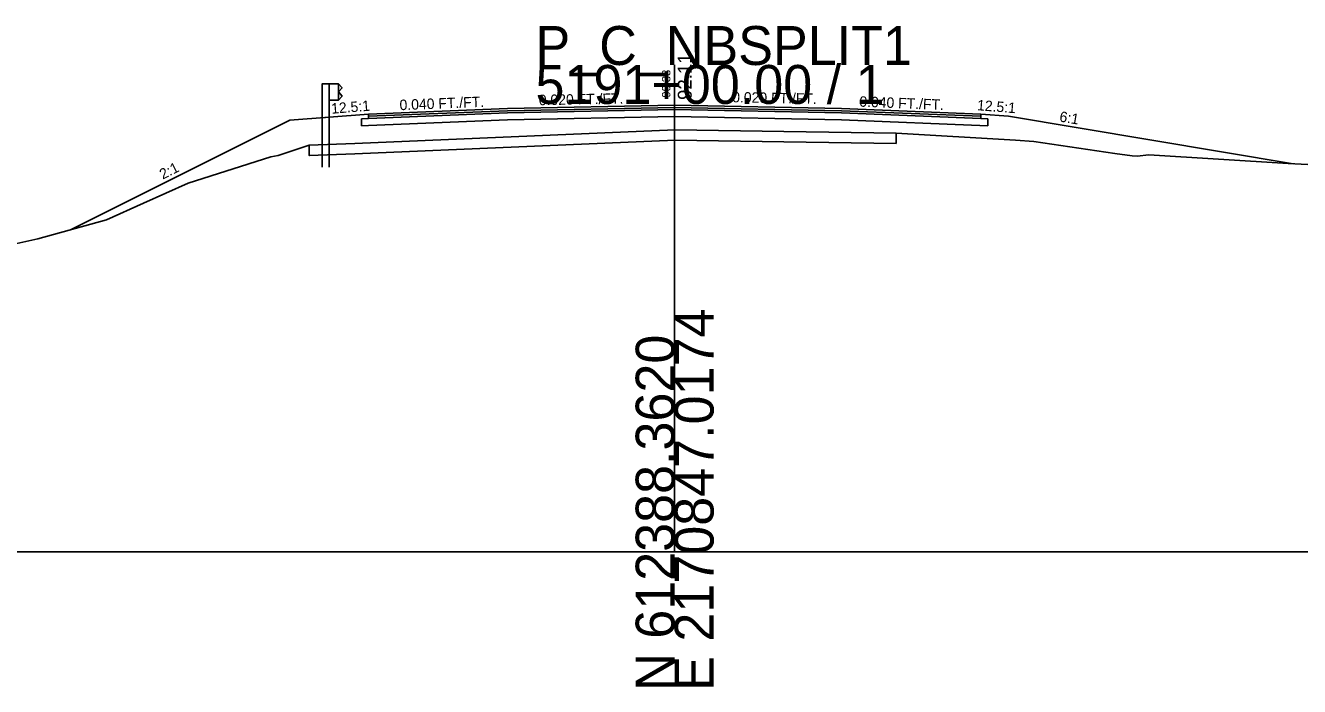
# Model space of a CAD drawing. Extents: x -26 to 1303, y -3010 to 12038.
# Drawn here: x 103.4 to 194.9, y 8990.3 to 9037.8 of the extents above; entities that cross this region are included whole.
import ezdxf

# ---------------------------------------------------------------- set-up
doc = ezdxf.new("R2010")
doc.units = 0
for name, color, linetype in [('RD_GPK_XS_Cell', 7, 'Continuous'), ('RD_PD_Final_TrvlWay', 7, 'Continuous'), ('RD_XS_Base', 7, 'Continuous'), ('RD_XS_ExGround', 7, 'Continuous'), ('RD_XS_ExPaveRet', 7, 'Continuous'), ('RD_XS_GR', 7, 'Continuous'), ('RD_XS_Greenside', 7, 'Continuous'), ('RD_XS_Pave', 7, 'Continuous'), ('RD_XS_PaveOvlay_CP', 7, 'Continuous'), ('RD_XS_TieSlope', 7, 'Continuous'), ('RD_XS_TX_Elev_EX', 7, 'Continuous'), ('RD_XS_TX_Elev_PR', 7, 'Continuous'), ('RD_XS_TX_ShdSlope', 7, 'Continuous'), ('RD_XS_TX_Slope', 7, 'Continuous')]:
    doc.layers.add(name, color=color, linetype=linetype)

msp = doc.modelspace()

# ---------------------------------------------------------------- linework, layer by layer
at = {"layer": 'RD_GPK_XS_Cell'}
for p, q in [((150, 9000), (150, 9035)), ((0, 9000), (150, 9000)), ((150, 9000), (300, 9000))]:
    msp.add_line(p, q, dxfattribs=at)
at = {"layer": 'RD_PD_Final_TrvlWay'}
for p, q in [((125.167, 9031.246), (124.667, 9031.206)), ((124.667, 9031.206), (124.667, 9027.641)), ((125.167, 9027.641), (125.167, 9031.246))]:
    msp.add_line(p, q, dxfattribs=at)
at = {"layer": 'RD_XS_Base'}
for p, q in [((150, 9031.794), (138, 9031.554)), ((150, 9031.794), (150, 9031.953)), ((150, 9031.953), (150, 9031.953)), ((150, 9031.953), (150, 9031.953)), ((150, 9031.953), (150, 9031.294)), ((150, 9031.294), (150, 9031.794)), ((150, 9031.794), (150, 9031.794)), ((150, 9031.794), (150, 9031.794)), ((150, 9031.794), (150, 9031.794)), ((162, 9031.554), (150, 9031.794)), ((128, 9031.154), (127.5, 9031.134)), ((127.5, 9031.134), (127.5, 9031.134)), ((127.5, 9031.134), (127.5, 9030.634)), ((138, 9031.554), (128, 9031.154)), ((128, 9031.154), (128, 9031.154)), ((128, 9030.654), (138, 9031.054)), ((138, 9031.554), (138, 9031.554)), ((138, 9031.054), (150, 9031.294)), ((138, 9031.054), (138, 9031.054)), ((150, 9031.294), (150, 9031.294)), ((150, 9031.294), (150, 9031.294)), ((150, 9031.294), (162, 9031.054)), ((172, 9031.154), (162, 9031.554)), ((162, 9031.054), (172.5, 9030.634)), ((164, 9031.474), (164, 9031.474)), ((164, 9030.974), (164, 9030.974)), ((172.5, 9031.134), (172, 9031.154)), ((172, 9031.154), (172, 9031.154)), ((172.5, 9030.634), (172.5, 9031.134)), ((172.5, 9031.134), (172.5, 9031.134)), ((127.5, 9030.634), (128, 9030.654)), ((128, 9030.654), (128, 9030.654))]:
    msp.add_line(p, q, dxfattribs=at)
at = {"layer": 'RD_XS_ExGround'}
msp.add_lwpolyline([(99.903, 9021.544), (104.227, 9022.497), (109.184, 9023.864), (111.823, 9025.062), (115.033, 9026.497), (120.993, 9028.395), (121.504, 9028.487), (123.742, 9029.23), (127.01, 9029.357), (150.046, 9030.335), (157.836, 9030.227), (165.917, 9030.109), (174.502, 9029.583), (175.807, 9029.5), (181.641, 9028.638), (182.873, 9028.465), (183.248, 9028.443), (184.081, 9028.547), (194.08, 9027.923), (200.187, 9027.606)], dxfattribs=at)
at = {"layer": 'RD_XS_ExPaveRet'}
for p, q in [((150.046, 9030.335), (127.01, 9029.357)), ((157.836, 9030.227), (150.046, 9030.335)), ((165.917, 9030.109), (157.836, 9030.227)), ((127.01, 9029.357), (123.742, 9029.23))]:
    msp.add_line(p, q, dxfattribs=at)
for points in [[(157.836, 9030.227), (150.046, 9030.335), (150.046, 9030.335), (127.01, 9029.357), (127.01, 9029.357), (123.742, 9029.23), (123.742, 9029.23), (123.742, 9028.48), (123.742, 9028.48), (123.742, 9028.48), (127.01, 9028.607), (127.01, 9028.607), (150.046, 9029.585), (150.046, 9029.585), (157.836, 9029.477), (157.836, 9029.477), (165.917, 9029.359), (165.917, 9030.109), (165.917, 9030.109), (157.836, 9030.227), (157.836, 9030.227)], [(123.742, 9029.23), (123.742, 9028.48), (127.01, 9028.607), (150.046, 9029.585), (157.836, 9029.477), (165.917, 9029.359), (165.917, 9030.109)]]:
    msp.add_lwpolyline(points, dxfattribs=at)
at = {"layer": 'RD_XS_GR'}
for points in [[(125.167, 9033.641), (125.167, 9031.246), (124.667, 9031.206), (124.667, 9033.641), (124.917, 9033.641), (125.167, 9033.641)], [(125.834, 9033.641), (125.834, 9032.474), (125.167, 9032.474), (125.167, 9033.641), (125.834, 9033.641)], [(125.834, 9033.641), (125.834, 9033.641), (125.834, 9033.641), (125.834, 9032.474), (126.105, 9032.766), (126.105, 9032.766), (125.834, 9033.058), (125.834, 9033.058), (126.105, 9033.349), (126.105, 9033.349), (125.834, 9033.641)]]:
    msp.add_lwpolyline(points, dxfattribs=at)
at = {"layer": 'RD_XS_Greenside'}
for p, q in [((122.355, 9031.021), (106.636, 9023.162)), ((174, 9031.312), (194.449, 9027.904))]:
    msp.add_line(p, q, dxfattribs=at)
at = {"layer": 'RD_XS_Pave'}
for p, q in [((138, 9031.872), (128, 9031.472)), ((150, 9032.112), (138, 9031.872)), ((150, 9031.953), (138, 9031.713)), ((138, 9031.713), (150, 9031.953)), ((138, 9031.872), (138, 9031.872)), ((138, 9031.554), (150, 9031.794)), ((162, 9031.872), (150, 9032.112)), ((150, 9032.112), (150, 9032.112)), ((150, 9032.112), (150, 9032.112)), ((150, 9031.794), (150, 9031.953)), ((150, 9031.953), (150, 9031.953)), ((150, 9031.953), (150, 9031.953)), ((150, 9031.953), (150, 9031.953)), ((150, 9031.953), (150, 9031.953)), ((150, 9031.953), (162, 9031.713)), ((162, 9031.713), (150, 9031.953)), ((150, 9031.953), (150, 9031.953)), ((150, 9031.953), (150, 9031.953)), ((150, 9031.953), (150, 9031.794)), ((150, 9031.794), (150, 9031.794)), ((150, 9031.794), (150, 9031.794)), ((150, 9031.794), (162, 9031.554)), ((172, 9031.472), (162, 9031.872)), ((164, 9031.792), (164, 9031.792)), ((138, 9031.713), (128, 9031.313)), ((128, 9031.313), (138, 9031.713)), ((128, 9031.154), (138, 9031.554)), ((128, 9031.472), (128, 9031.472)), ((128, 9031.472), (128, 9031.313)), ((128, 9031.313), (128, 9031.313)), ((128, 9031.313), (128, 9031.154)), ((138, 9031.713), (138, 9031.713)), ((138, 9031.713), (138, 9031.713)), ((138, 9031.554), (138, 9031.554)), ((162, 9031.713), (172, 9031.313)), ((172, 9031.313), (162, 9031.713)), ((162, 9031.554), (172, 9031.154)), ((164, 9031.633), (164, 9031.633)), ((164, 9031.633), (164, 9031.633)), ((164, 9031.474), (164, 9031.474)), ((172, 9031.313), (172, 9031.472)), ((172, 9031.472), (172, 9031.472)), ((172, 9031.154), (172, 9031.313)), ((172, 9031.313), (172, 9031.313))]:
    msp.add_line(p, q, dxfattribs=at)
at = {"layer": 'RD_XS_PaveOvlay_CP'}
for p, q in [((128, 9031.472), (138, 9031.872)), ((138, 9031.872), (150, 9032.112)), ((150, 9032.112), (162, 9031.872)), ((162, 9031.872), (172, 9031.472))]:
    msp.add_line(p, q, dxfattribs=at)
at = {"layer": 'RD_XS_TieSlope'}
for p, q in [((128, 9031.472), (122.355, 9031.021)), ((172, 9031.472), (174, 9031.312))]:
    msp.add_line(p, q, dxfattribs=at)

# ---------------------------------------------------------------- texts
at = {"layer": 'RD_GPK_XS_Cell'}
for s, p in [('P_C_NBSPLIT1', (140, 9035)), ('5191+00.00 / 1', (140, 9032.2))]:
    msp.add_text(s, height=2.8, dxfattribs=at).set_placement(p)
for s, p in [('E 2170847.0174', (152.8, 8990)), ('N 612388.3620', (150, 8990))]:
    msp.add_text(s, height=2.8, rotation=90, dxfattribs=at).set_placement(p)
at = {"layer": 'RD_XS_TX_Elev_EX'}
msp.add_text('90.33', height=0.6, rotation=90, dxfattribs=at).set_placement((149.692, 9032.651))
at = {"layer": 'RD_XS_TX_Elev_PR'}
msp.add_text('92.11', height=1, rotation=90, dxfattribs=at).set_placement((151.224, 9032.488))
at = {"layer": 'RD_XS_TX_ShdSlope'}
for rotation, p in [(4.57392, (125.35, 9031.49)), (355.42608, (171.711, 9031.751))]:
    msp.add_text('12.5:1', height=0.75, rotation=rotation, dxfattribs=at).set_placement(p)
at = {"layer": 'RD_XS_TX_Slope'}
for s, rotation, p in [('0.040 FT./FT.', 2.29061, (130.247, 9031.748)), ('0.020 FT./FT.', 1.14576, (140.248, 9032.103)), ('0.020 FT./FT.', 358.85424, (154.13, 9032.318)), ('0.040 FT./FT.', 357.70939, (163.262, 9032.007)), ('6:1', 350.53768, (177.614, 9030.943)), ('2:1', 26.56505, (113.215, 9026.752))]:
    msp.add_text(s, height=0.75, rotation=rotation, dxfattribs=at).set_placement(p)

doc.saveas('drawing.dxf')
